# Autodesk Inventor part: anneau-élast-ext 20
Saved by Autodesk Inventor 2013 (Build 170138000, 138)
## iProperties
Created: 2012-12
Part Number: anneau-élast-ext 20
Material: Générique
Document SubType Name: Modeling
Designer: jost thierry
Density: 1 g/cm^3
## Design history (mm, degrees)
node "anneau-élast-ext 201"
node "anneau-élast-ext 20"
node "Base1"
